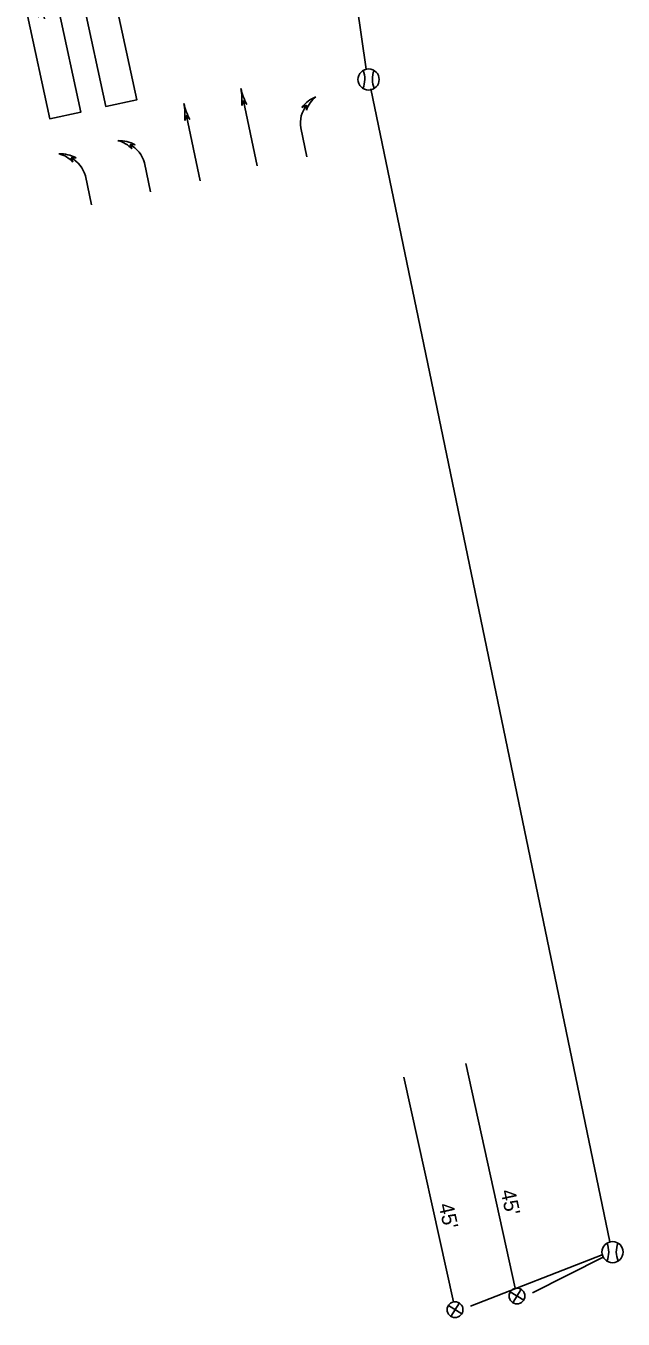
# Model space of a CAD drawing. Extents: x 596176 to 605330, y 332416 to 402398.
# Drawn here: x 604789.3 to 604902.1, y 339003 to 339247.6 of the extents above; entities that cross this region are included whole.
import ezdxf

# ---------------------------------------------------------------- set-up
doc = ezdxf.new("R2010")
doc.units = 0
for name, color, linetype in [('P_SIG', 7, 'Continuous'), ('P_SIG_Bold', 7, 'Continuous'), ('P_SIG_Conduit', 7, 'Continuous'), ('P_SIG_Loops', 7, 'Continuous')]:
    doc.layers.add(name, color=color, linetype=linetype)

# ---------------------------------------------------------------- blocks, each defined once
blk = doc.blocks.new('_U305')
at = {"layer": 'P_SIG_Loops'}
for p, q in [((-0.055, -0.084), (0.052, 0.081)), ((0.056, -0.083), (-0.053, 0.082)), ((0, 0), (0, -0.229)), ((-0.105, -0.001), (0.099, -0.001))]:
    blk.add_line(p, q, dxfattribs=at)
blk.add_lwpolyline([(0, -0.229), (1.524, -0.229), (1.524, 0.229), (0, 0.229)], close=True, dxfattribs=at)
blk = doc.blocks.new('_U330')
at = {"layer": 'P_SIG_Bold'}
for p, q in [((-3.429, 0), (-0.114, 0)), ((-0.081, 0.081), (0.081, -0.081)), ((0.081, 0.081), (-0.081, -0.081))]:
    blk.add_line(p, q, dxfattribs=at)
blk.add_circle((0, 0), 0.114, dxfattribs=at)
blk.add_text("45'", height=0.2134, dxfattribs=at).set_placement((-1.528, 0.092))
blk = doc.blocks.new('_U227')
at = {"layer": 'P_SIG'}
blk.add_circle((0, 0.01), 6.1, dxfattribs=at)
for centre, start, end in [((-15.46, 0.12), 336.67411, 22.52722), ((15.45, 0.15), 157.57508, 203.4282)]:
    blk.add_arc(centre, 13.28, start, end, dxfattribs=at)
blk = doc.blocks.new('_U319')
at = {"layer": 'P_SIG'}
for p, q in [((-0.675, 0.115), (-0.743, 0.129)), ((-0.725, 0.057), (-0.743, 0.129)), ((-0.017, -0.02), (-0.443, -0.02))]:
    blk.add_line(p, q, dxfattribs=at)
for centre, radius, start, end in [((-0.479, 0.454), 0.392, 205.2667, 239.9151), ((-0.377, 0.361), 0.462, 189.3153, 221.1715), ((-0.412, 0.421), 0.442, 221.4708, 266.0347)]:
    blk.add_arc(centre, radius, start, end, dxfattribs=at)
blk = doc.blocks.new('_U318')
at = {"layer": 'P_SIG'}
blk.add_line((-0.017, -0.02), (-0.975, -0.02), dxfattribs=at)
blk.add_lwpolyline([(-0.914, 0.018), (-0.975, -0.02), (-0.914, -0.058)], dxfattribs=at)
for centre, start, end in [((-1.158, 0.78), 270, 287.7623), ((-1.158, -0.819), 72.2377, 90)]:
    blk.add_arc(centre, 0.799, start, end, dxfattribs=at)
blk = doc.blocks.new('_U320')
at = {"layer": 'P_SIG'}
for p, q in [((-0.725, -0.096), (-0.743, -0.168)), ((-0.675, -0.154), (-0.743, -0.168)), ((-0.017, -0.02), (-0.443, -0.02))]:
    blk.add_line(p, q, dxfattribs=at)
for centre, radius, start, end in [((-0.377, -0.401), 0.462, 138.8285, 170.6847), ((-0.479, -0.493), 0.392, 120.0849, 154.7333), ((-0.412, -0.46), 0.442, 93.9653, 138.5292)]:
    blk.add_arc(centre, radius, start, end, dxfattribs=at)

msp = doc.modelspace()

# ---------------------------------------------------------------- linework, layer by layer
at = {"layer": 'P_SIG_Conduit'}
for points in [[(604850.05, 339263.88), (604853.59, 339239.38)], [(604854.42, 339235.65), (604899.59, 339017.6)]]:
    msp.add_lwpolyline(points, dxfattribs=at)
at = {"layer": 'P_SIG_Loops'}
for p, q in [((604873.29, 339005.43), (604898.18, 339015.19)), ((604885, 339007.99), (604898.35, 339014.74))]:
    msp.add_line(p, q, dxfattribs=at)

# ---------------------------------------------------------------- block references
at = {"layer": 'P_SIG', "xscale": 13.123333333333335, "yscale": 13.123333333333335, "rotation": -78.03640385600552}
for name, p in [('_U318', (604833.28, 339220.92)), ('_U318', (604822.51, 339218.09)), ('_U319', (604842.65, 339222.66)), ('_U320', (604813.12, 339216.04)), ('_U320', (604801.97, 339213.55))]:
    msp.add_blockref(name, p, dxfattribs=at)
at = {"layer": 'P_SIG_Conduit', "xscale": 0.32808333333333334, "yscale": 0.32808333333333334}
for p in [(604854.02, 339237.42), (604900.12, 339015.67)]:
    msp.add_blockref('_U227', p, dxfattribs=at)
at = {"layer": 'P_SIG_Loops'}
for name, p, xscale, yscale, rotation in [('_U305', (604803.07, 339252.51), 13.123333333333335, 13.123333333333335, -77.81394907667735), ('_U305', (604792.49, 339250.17), 13.123333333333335, 13.123333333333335, -77.81394907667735), ('_U330', (604882.07, 339007.37), 13.123333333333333, 13.123333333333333, -77.60993475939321), ('_U330', (604870.36, 339004.79), 13.123333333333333, 13.123333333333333, -77.60993475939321)]:
    msp.add_blockref(name, p, dxfattribs=dict(at, xscale=xscale, yscale=yscale, rotation=rotation))

doc.saveas('drawing.dxf')
